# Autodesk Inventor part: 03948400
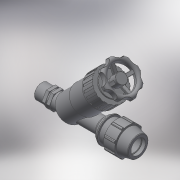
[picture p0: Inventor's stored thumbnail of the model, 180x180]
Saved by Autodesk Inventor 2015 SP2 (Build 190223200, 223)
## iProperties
Created: 2017-02
Part Number: 03948400
Material: Generic
Description: PLASSON ANGLE SEAT VALVE 40-1.1/4"
Document SubType Name: Modeling
Designer: KIM
Mass: 1130.48 g
Surface Area: 1497.94 cm^2
Volume: 1130.48 cm^3
Density: 1 g/cm^3
Appearance: Default
Author: KIM
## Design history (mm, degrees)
derived "03048-03948.ipt"
feature "Solid1::03048-03948.ipt"
tag "TaggingFeature1"
body "Solid1"
other parameters: "d4" = 12.45833, "d5" = 29.9, "d7" = 82, "d11" = 4.27143, "d13" = 120 deg, "d14" = 56, "d15" = 12 deg, "d16" = 71.34, "d18" = 2, "d19" = 35 deg, "d20" = 17.5 deg, "d21" = 76.26, "d23" = 0, "d25" = 360 deg, "d27" = 1.64, "d33" = 0.8, "d42" = 35.88, "d43" = 2.46, "d46" = 1.2, "d63" = 84, "d67" = 61.5, "d96" = 7.475, "d128" = 299, "d159" = 2, "d165" = 162, "d167" = 97.2, "d168" = 29.16, "d169" = 29.16, "d170" = 90 deg, "d171" = 70 deg, "d172" = 23.328, "d173" = 68.04, "d174" = 68.04, "d175" = 87.48, "d176" = 135 deg, "d177" = 77.76, "d178" = 72.9, "d179" = 40.5, "d180" = 162, "d182" = 23.328, "d183" = 64.152, "d190" = 45 deg, "d191" = 59.8, "d192" = 3.6, "d193" = 4.52, "d194" = 2.26, "d195" = 84.8556, "d198" = 0, "d199" = 36.45, "d200" = 113, "d204" = 360 deg, "d209" = 0, "d213" = 4.86, "d216" = 360 deg, "d220" = 82.62, "d221" = 3.39, "d222" = 3.39, "d223" = 6.78, "d227" = 3.39, "d229" = 0, "d230" = 0.9, "d232" = 360 deg, "d234" = 0.9, "d235" = 0.9, "d237" = 360 deg, "d239" = 1.44, "d241" = 0.9, "d249" = 41.91, "d250" = 45 deg, "d251" = 32, "d252" = 299, "d253" = 22, "d254" = 7.33333, "d255" = 3.66667, "d256" = 42, "d258" = 0, "d260" = 0, "d261" = 0.8382, "d265" = 0, "E_" = 82, "l_" = 84, "H_" = 299, "d224" = 113, "G_" = 41.91, "l_2" = 22, "d202" = 87.48, "d214" = 97.2, "d218" = 97.2, "d225" = 97.2, "d226" = 68.04
